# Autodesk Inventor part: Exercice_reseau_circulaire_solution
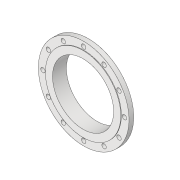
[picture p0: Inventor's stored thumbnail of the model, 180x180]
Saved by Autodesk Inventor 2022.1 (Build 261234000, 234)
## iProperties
Created: 2018-03
Part Number: Exercice_reseau_circulaire_solution
Material: Générique
Document SubType Name: Modeling
Designer: booth09-mgr2
Density: 1 g/cm^3
Appearance: Par défaut
Stock Number: bri-Fonte-300
Mass: 2611.83 g
Surface Area: 3121.94 cm^2
Volume: 2611.83 cm^3
g1: 370,000 mm
D: 445,000 mm
Author: booth09-mgr2
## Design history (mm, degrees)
sketch "Esquisse1"
  geometry: L1 (0, 0)-(0, 68); L2 (-222.5, 3)-(-222.5, 26); L3 (-222.5, 26)-(-172.5, 26); L4 (-172.5, 26)-(-161.5, 58); L5 (-161.5, 58)-(-161.5, 68); L6 (-161.5, 68)-(-150, 68); L7 (-222.5, 3)-(-185, 3); L8 (-185, 3)-(-185, 0); L9 (-185, 0)-(-150, 0); L10 (-150, 0)-(-150, 68)
  constraints: 21 end point, 4 perpendicular, 2 horizontal alignment, 2 vertical, 1 horizontal, 1 parallel
  dimensions: "g1" = 370 diameter of L8 L1; "D" = 445 diameter of L2 L1; "d" = 323 diameter of L5 L1; "d4" = 3 distance of L7.end L8.end; "d5" = 10 distance of L4.end L5.end; "h1" = 68 distance of L1.start L1.end; "d7" = 50 distance of L2.end L3.end; "DN" = 300 diameter of L10 L1; "b" = 26 distance between parallel lines of L9 L3
revolve "Révolution1" sketch "Esquisse1" stored, may be unused: angle "d9" = 90 deg
fillet "Congé1" dims "d10" = 2
node "Plan de construction1"
sketch "Esquisse2"
  geometry: L1 (0, 0)-(150, 0); 2 further points
  constraints: 2 end point, 1 horizontal, 1 symmetric about line, 1 vertical alignment
  dimensions: "C1" = 400 distance of point (0, -200) point (0, 200)
hole "Perçage1" sketch "Esquisse2" diameter "O" = 22; stored, may be unused: countersink angle "d21" = 90 deg, drill point angle "d23" = 118 deg; dims "d18" = 6, "d19" = 4, "d20" = 2, "d22" = 8
pattern_circular "Réseau circulaire2" dims angle "d28" = 360 deg
node "Solide1"
